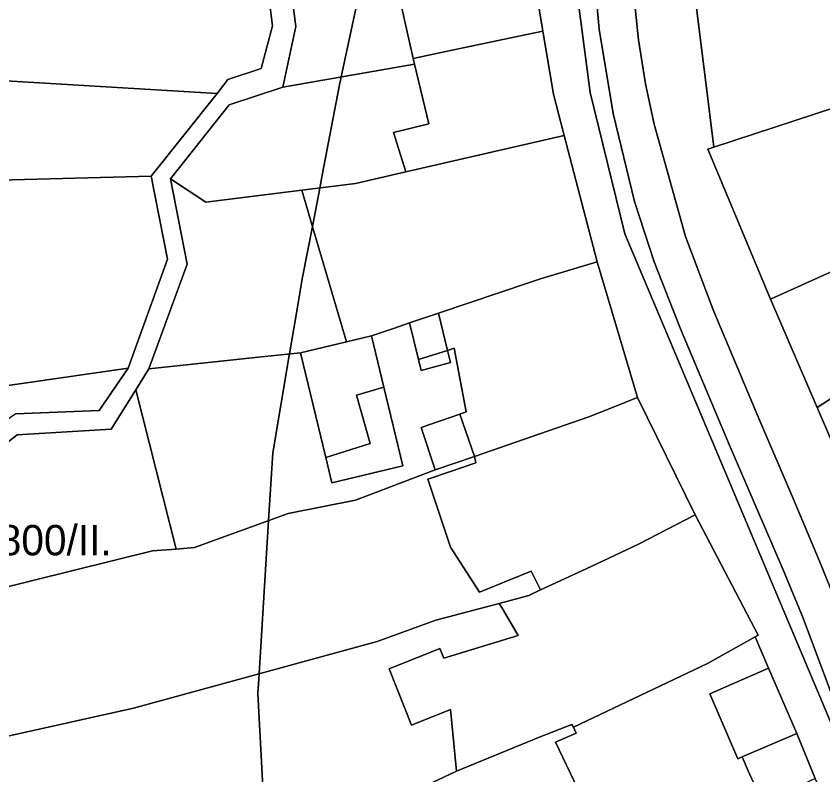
# Model space of a CAD drawing. Extents: x -522079 to -518833, y -1142400 to -1139961.
# Drawn here: x -520471.7 to -520338.9, y -1141042.9 to -1140918 of the extents above; entities that cross this region are included whole.
import ezdxf

# ---------------------------------------------------------------- set-up
doc = ezdxf.new("R2010")
doc.units = 0
for name, color, linetype in [('95590013', 7, 'Continuous'), ('95630013', 7, 'Continuous'), ('95640013', 7, 'Continuous'), ('95660013', 7, 'Continuous')]:
    doc.layers.add(name, color=color, linetype=linetype)

msp = doc.modelspace()

# ---------------------------------------------------------------- linework, layer by layer
at = {"layer": '95590013'}
for points in [[(-520438.64, -1140930.72), (-520527.38, -1140925.42), (-520549.95, -1140907.16), (-520539.31, -1140891.51), (-520538.57, -1140892.18), (-520531.52, -1140898.7), (-520514.41, -1140910.27), (-520468.41, -1140914.85), (-520451.95, -1140915.2), (-520430.59, -1140910.8), (-520429.5, -1140919.57), (-520431.36, -1140926.59), (-520436.87, -1140928.43)], [(-520449.47, -1140944.32), (-520524.57, -1140946.3), (-520536.98, -1140945.57), (-520562.58, -1140925.73), (-520549.95, -1140907.16), (-520527.38, -1140925.42), (-520438.64, -1140930.72)], [(-520529.52, -1140984.06), (-520584.75, -1140957.97), (-520562.58, -1140925.73), (-520536.98, -1140945.57), (-520524.57, -1140946.3), (-520449.47, -1140944.32), (-520446.79, -1140958), (-520453.28, -1140975.93), (-520475.75, -1140979.18), (-520509.19, -1140985.26), (-520518.62, -1140988.49)], [(-520406.14, -1140925.89), (-520403.8, -1140935.74), (-520409.58, -1140937.12), (-520407.58, -1140943.63), (-520415.85, -1140945.56), (-520424.71, -1140946.66), (-520440.46, -1140948.61), (-520446.27, -1140944.76), (-520436.62, -1140932.6), (-520427.82, -1140929.68)], [(-520456.05, -1140986), (-520451.99, -1140979.48), (-520445.36, -1141005.71), (-520449.27, -1141006.02), (-520508.38, -1141020.64), (-520531.57, -1141026.89), (-520547.82, -1141024.57), (-520543.9, -1141011.82), (-520529.65, -1140994.14), (-520523.73, -1140993.96), (-520516.37, -1140999.34), (-520507.31, -1140999.82), (-520500.6, -1141005.26), (-520489.07, -1141005.5), (-520479.55, -1140993.19), (-520471.51, -1140986.91)], [(-520387.31, -1141013.36), (-520392.22, -1141014.66), (-520402.65, -1141017.41), (-520412.3, -1141020.92), (-520452.37, -1141031.92), (-520497.24, -1141041.88), (-520498.56, -1141042.19), (-520508.38, -1141020.64), (-520449.27, -1141006.02), (-520445.36, -1141005.71), (-520442.37, -1141005.47), (-520426.91, -1140999.86), (-520415.87, -1140997.65), (-520402.73, -1140992.69), (-520396.26, -1140990.46), (-520396.06, -1140991.53), (-520400.05, -1140992.89), (-520403.95, -1140994.2), (-520400.21, -1141005.43), (-520395.43, -1141012.8), (-520386.94, -1141009.33), (-520385.38, -1141012.44)], [(-520400.21, -1141032.13), (-520399.24, -1141042.3), (-520408.06, -1141046.45), (-520431.05, -1141052.26), (-520487.67, -1141063.72), (-520493.42, -1141050.65), (-520491.27, -1141049.7), (-520494.03, -1141043.4), (-520496.2, -1141044.35), (-520497.24, -1141041.88), (-520452.37, -1141031.92), (-520412.3, -1141020.92), (-520402.65, -1141017.41), (-520392.22, -1141014.66), (-520391.74, -1141015.46), (-520389.08, -1141019.93), (-520401.32, -1141023.68), (-520401.95, -1141022.11), (-520410.31, -1141025.45), (-520406.62, -1141034.69)]]:
    msp.add_lwpolyline(points, close=True, dxfattribs=at)
at = {"layer": '95630013'}
for points in [[(-520471.76, -1140983.46), (-520458.05, -1140982.9), (-520453.28, -1140975.93), (-520446.79, -1140958), (-520449.47, -1140944.32), (-520438.64, -1140930.72), (-520436.87, -1140928.43), (-520431.36, -1140926.59), (-520429.5, -1140919.57), (-520430.59, -1140910.8), (-520434.57, -1140885.18), (-520431.14, -1140872), (-520431.21, -1140855.94), (-520429.98, -1140844.23), (-520420.46, -1140841.58), (-520420.15, -1140839.19), (-520417.22, -1140816.48), (-520423.57, -1140810.07), (-520432.63, -1140806.38), (-520444.45, -1140805.57), (-520462.48, -1140800.42), (-520469.2, -1140792.72)], [(-520426.8, -1140910.65), (-520425.67, -1140919.72), (-520427.82, -1140929.68), (-520436.62, -1140932.6), (-520446.27, -1140944.76), (-520443.57, -1140958.81), (-520449.86, -1140976.07), (-520451.99, -1140979.48), (-520456.05, -1140986), (-520471.51, -1140986.91), (-520479.55, -1140993.19)]]:
    msp.add_lwpolyline(points, dxfattribs=at)
at = {"layer": '95640013'}
for points in [[(-520334.74, -1141054.84), (-520340.18, -1141043.47), (-520343.25, -1141036.1), (-520347.88, -1141025.34), (-520350.1, -1141020.17), (-520349.61, -1141019.9), (-520359.98, -1141000.07), (-520369.44, -1140980.74), (-520376.07, -1140958.44), (-520381.51, -1140937.64), (-520383.27, -1140930.85), (-520385, -1140920.46), (-520387.91, -1140902.86), (-520388.38, -1140878.81), (-520385.81, -1140848.46), (-520386.02, -1140848.4), (-520386.88, -1140823.39), (-520383.07, -1140848.38), (-520382.78, -1140878.64), (-520380.96, -1140902.07), (-520377.25, -1140930.57), (-520371.53, -1140953.82), (-520335.76, -1141038.73)], [(-520335.76, -1141038.73), (-520371.53, -1140953.82), (-520377.25, -1140930.57), (-520380.96, -1140902.07)], [(-520335.75, -1141034.28), (-520342.18, -1141017.11), (-520345.5, -1141009.13), (-520354.36, -1140988.48), (-520362.35, -1140969.44), (-520366.71, -1140958.45), (-520369.93, -1140948.53), (-520373.47, -1140934.03), (-520375.75, -1140920.12), (-520377.36, -1140902.45)], [(-520377.36, -1140902.45), (-520375.75, -1140920.12), (-520373.47, -1140934.03), (-520369.93, -1140948.53), (-520366.71, -1140958.45), (-520362.35, -1140969.44), (-520354.36, -1140988.48), (-520345.5, -1141009.13), (-520342.18, -1141017.11), (-520335.75, -1141034.28)], [(-520371.26, -1140902.9), (-520369.28, -1140921.92), (-520368.13, -1140929.14), (-520366.72, -1140935.8), (-520361.56, -1140954.25), (-520356.97, -1140966.32), (-520349.32, -1140984.59), (-520343.82, -1140997.39), (-520339.2, -1141008.34), (-520330.66, -1141029.65)], [(-520330.66, -1141029.65), (-520339.2, -1141008.34), (-520343.82, -1140997.39), (-520349.32, -1140984.59), (-520356.97, -1140966.32), (-520361.56, -1140954.25), (-520366.72, -1140935.8), (-520368.13, -1140929.14), (-520369.28, -1140921.92), (-520371.26, -1140902.9)], [(-520359.88, -1140915.32), (-520358.24, -1140928.5), (-520356.86, -1140939.57), (-520357.85, -1140939.9), (-520347.56, -1140964.58), (-520339.88, -1140982.4), (-520328.8, -1141008.12)]]:
    msp.add_lwpolyline(points, dxfattribs=at)
for points in [[(-520387.91, -1140902.86), (-520385, -1140920.46), (-520391.59, -1140921.84), (-520401.77, -1140923.98), (-520406.37, -1140924.94), (-520410.31, -1140907.35), (-520394.51, -1140903.6)], [(-520410.31, -1140907.35), (-520406.37, -1140924.94), (-520406.14, -1140925.89), (-520427.82, -1140929.68), (-520425.67, -1140919.72), (-520426.8, -1140910.65)], [(-520359.88, -1140915.32), (-520357.13, -1140915.06), (-520357.38, -1140911.92), (-520338.02, -1140909.41), (-520336.89, -1140913.16), (-520329.64, -1140912.5), (-520328.35, -1140930.16), (-520333.64, -1140931.91), (-520356.86, -1140939.57), (-520358.24, -1140928.5)], [(-520385, -1140920.46), (-520383.27, -1140930.85), (-520381.51, -1140937.64), (-520407.58, -1140943.63), (-520409.58, -1140937.12), (-520403.8, -1140935.74), (-520406.14, -1140925.89), (-520406.37, -1140924.94), (-520401.77, -1140923.98), (-520391.59, -1140921.84)], [(-520301.23, -1140944.23), (-520303.52, -1140945.28), (-520311.37, -1140948.65), (-520312.42, -1140949.1), (-520330.57, -1140956.9), (-520333.07, -1140958.03), (-520347.56, -1140964.58), (-520357.85, -1140939.9), (-520356.86, -1140939.57), (-520333.64, -1140931.91), (-520328.35, -1140930.16), (-520327.1, -1140929.75), (-520320.68, -1140927.43), (-520309.29, -1140923.33), (-520304.25, -1140936.55), (-520303.17, -1140939.4), (-520297.35, -1140935.94), (-520295.5, -1140940.8), (-520301.37, -1140943.86)], [(-520424.71, -1140946.66), (-520415.85, -1140945.56), (-520407.58, -1140943.63), (-520381.51, -1140937.64), (-520376.07, -1140958.44), (-520385.4, -1140961.22), (-520387.23, -1140961.84), (-520402.17, -1140966.88), (-520406.94, -1140968.49), (-520409.61, -1140969.39), (-520413.21, -1140970.61), (-520417.34, -1140971.6), (-520422.88, -1140952.85)], [(-520443.57, -1140958.81), (-520446.27, -1140944.76), (-520440.46, -1140948.61), (-520424.71, -1140946.66), (-520422.88, -1140952.85), (-520417.34, -1140971.6), (-520424.88, -1140973.41), (-520431.3, -1140974.09), (-520449.86, -1140976.07)], [(-520333.07, -1140958.03), (-520330.57, -1140956.9), (-520312.42, -1140949.1), (-520311.37, -1140948.65), (-520303.52, -1140945.28), (-520300.74, -1140948.36), (-520299.04, -1140950.24), (-520294.61, -1140946.2), (-520278.46, -1140964.1), (-520288.51, -1140973.21), (-520288.83, -1140973.5), (-520322.15, -1141002.36), (-520328.8, -1141008.12), (-520339.88, -1140982.4), (-520336.31, -1140980.12), (-520328.21, -1140974.96), (-520328.8, -1140974.04), (-520325.3, -1140971.81)], [(-520333.07, -1140958.03), (-520325.3, -1140971.81), (-520328.8, -1140974.04), (-520328.21, -1140974.96), (-520336.31, -1140980.12), (-520339.88, -1140982.4), (-520347.56, -1140964.58)], [(-520369.44, -1140980.74), (-520375.92, -1140983.35), (-520377.45, -1140983.97), (-520396.26, -1140990.46), (-520398.66, -1140983.49), (-520397.64, -1140983.14), (-520399.62, -1140972.67), (-520400.73, -1140973.02), (-520402.17, -1140966.88), (-520387.23, -1140961.84), (-520385.4, -1140961.22), (-520376.07, -1140958.44)], [(-520400.73, -1140973.02), (-520405.49, -1140974.52), (-520406.94, -1140968.49), (-520402.17, -1140966.88)], [(-520402.73, -1140992.69), (-520415.87, -1140997.65), (-520426.91, -1140999.86), (-520442.37, -1141005.47), (-520445.36, -1141005.71), (-520451.99, -1140979.48), (-520449.86, -1140976.07), (-520431.3, -1140974.09), (-520424.88, -1140973.41), (-520420.75, -1140990.63), (-520419.75, -1140994.8), (-520408.08, -1140992), (-520411.18, -1140979.06), (-520413.21, -1140970.61), (-520409.61, -1140969.39), (-520406.94, -1140968.49), (-520405.49, -1140974.52), (-520405.06, -1140976.3), (-520400.22, -1140975.02), (-520400.73, -1140973.02), (-520399.62, -1140972.67), (-520397.64, -1140983.14), (-520398.66, -1140983.49), (-520405.04, -1140985.68)], [(-520424.88, -1140973.41), (-520417.34, -1140971.6), (-520413.21, -1140970.61), (-520411.18, -1140979.06), (-520415.7, -1140980.4), (-520413.45, -1140988.34), (-520420.75, -1140990.63)], [(-520405.49, -1140974.52), (-520400.73, -1140973.02), (-520400.22, -1140975.02), (-520405.06, -1140976.3)], [(-520453.28, -1140975.93), (-520458.05, -1140982.9), (-520471.76, -1140983.46), (-520483.03, -1140991.17), (-520490.41, -1141002.21), (-520499.42, -1141001.88), (-520518.62, -1140988.49), (-520509.19, -1140985.26), (-520475.75, -1140979.18)], [(-520420.75, -1140990.63), (-520413.45, -1140988.34), (-520415.7, -1140980.4), (-520411.18, -1140979.06), (-520408.08, -1140992), (-520419.75, -1140994.8)], [(-520382.88, -1141011.26), (-520385.38, -1141012.44), (-520386.94, -1141009.33), (-520395.43, -1141012.8), (-520400.21, -1141005.43), (-520403.95, -1140994.2), (-520400.05, -1140992.89), (-520396.06, -1140991.53), (-520396.26, -1140990.46), (-520377.45, -1140983.97), (-520375.92, -1140983.35), (-520369.44, -1140980.74), (-520359.98, -1141000.07), (-520369.28, -1141004.93), (-520377.08, -1141008.56)], [(-520396.26, -1140990.46), (-520402.73, -1140992.69), (-520405.04, -1140985.68), (-520398.66, -1140983.49)], [(-520385.38, -1141012.44), (-520382.88, -1141011.26), (-520377.08, -1141008.56), (-520369.28, -1141004.93), (-520359.98, -1141000.07), (-520349.61, -1141019.9), (-520350.1, -1141020.17), (-520357.91, -1141024.53), (-520380, -1141035.01), (-520380.26, -1141034.58), (-520385.48, -1141036.63), (-520399.24, -1141042.3), (-520400.21, -1141032.13), (-520406.62, -1141034.69), (-520410.31, -1141025.45), (-520401.95, -1141022.11), (-520401.32, -1141023.68), (-520389.08, -1141019.93), (-520391.74, -1141015.46), (-520392.22, -1141014.66), (-520387.31, -1141013.36)], [(-520367.77, -1141056.92), (-520370.31, -1141051.82), (-520375, -1141054.13), (-520382.96, -1141037.48), (-520379.56, -1141036.01), (-520380, -1141035.01), (-520357.91, -1141024.53), (-520350.1, -1141020.17), (-520347.88, -1141025.34), (-520357.55, -1141029.54), (-520352.93, -1141040.25), (-520352.22, -1141039.94), (-520351.25, -1141042.23), (-520348.84, -1141047.55), (-520360.31, -1141053.23)], [(-520352.22, -1141039.94), (-520352.93, -1141040.25), (-520357.55, -1141029.54), (-520347.88, -1141025.34), (-520343.25, -1141036.1)], [(-520375, -1141054.13), (-520370.31, -1141051.82), (-520367.77, -1141056.92), (-520380.42, -1141062.83), (-520390.79, -1141066.51), (-520425.4, -1141075.5), (-520431.05, -1141052.26), (-520408.06, -1141046.45), (-520399.24, -1141042.3), (-520385.48, -1141036.63), (-520380.26, -1141034.58), (-520380, -1141035.01), (-520379.56, -1141036.01), (-520382.96, -1141037.48)], [(-520352.22, -1141039.94), (-520343.25, -1141036.1), (-520340.18, -1141043.47), (-520348.84, -1141047.55), (-520351.25, -1141042.23)]]:
    msp.add_lwpolyline(points, close=True, dxfattribs=at)
at = {"layer": '95660013'}
for points in [[(-520430.7, -1141052.17), (-520431.36, -1141039.71), (-520431.9, -1141029.48), (-520431.7, -1141026.25), (-520430.15, -1141001.03), (-520429.47, -1140989.88), (-520426.74, -1140973.83), (-520426.7, -1140973.6), (-520425.34, -1140965.57), (-520424.61, -1140961.24), (-520422.95, -1140952.6), (-520421.74, -1140946.29), (-520421.33, -1140944.15), (-520418.53, -1140929.56), (-520418.2, -1140928), (-520413.94, -1140908.08)], [(-520413.94, -1140908.08), (-520418.2, -1140928), (-520418.53, -1140929.56), (-520421.33, -1140944.15), (-520421.74, -1140946.29), (-520422.95, -1140952.6), (-520424.61, -1140961.24), (-520425.34, -1140965.57), (-520426.7, -1140973.6), (-520426.74, -1140973.83), (-520429.47, -1140989.88), (-520430.15, -1141001.03), (-520431.7, -1141026.25), (-520431.9, -1141029.48), (-520431.36, -1141039.71), (-520430.7, -1141052.17)]]:
    msp.add_lwpolyline(points, dxfattribs=at)

# ---------------------------------------------------------------- texts
msp.add_text('65800/II.', height=5, rotation=360, dxfattribs=at).set_placement((-520482, -1141006.75))

doc.saveas('drawing.dxf')
